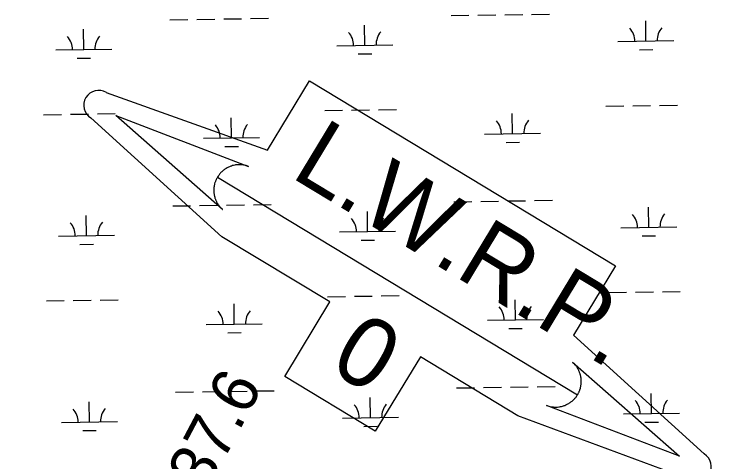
# Model space of a CAD drawing. Extents: x 3807117 to 3845308, y 337856 to 363736.
# Drawn here: x 3812085 to 3813343, y 356278 to 357078 of the extents above; entities that cross this region are included whole.
import ezdxf

# ---------------------------------------------------------------- set-up
doc = ezdxf.new("R2010")
doc.units = 0
for name, color, linetype in [('V-RIVR-EDGE', 7, 'Continuous'), ('V-RIVR-RANG-IDEN', 7, 'Continuous'), ('V-TOPO-WATR-IDEN', 7, 'Continuous'), ('V-WETL-SWMP', 7, 'Continuous')]:
    doc.layers.add(name, color=color, linetype=linetype)

msp = doc.modelspace()

# ---------------------------------------------------------------- linework, layer by layer
at = {"layer": 'V-RIVR-EDGE'}
msp.add_spline([(3811174.6, 356373.1), (3811188.7, 356370), (3811203.6, 356367.3), (3811222.1, 356356.8), (3811286.2, 356317.3), (3811338.6, 356278.8), (3811362.1, 356266.1), (3811376.1, 356260.1), (3811397.3, 356252.4), (3811428.9, 356236.1), (3811458.2, 356216.5), (3811472.2, 356207.9), (3811493.5, 356193.8), (3811502, 356194.7), (3811509.7, 356201), (3811518.8, 356201.5), (3811535.5, 356195.1), (3811546.8, 356183.3), (3811549.5, 356172.5), (3811555.8, 356158.4), (3811561.2, 356151.2), (3811563.9, 356150.7), (3811570.7, 356164.3), (3811577, 356167), (3811587, 356165.6), (3811593.3, 356157.4), (3811593.3, 356147.9), (3811590.5, 356127.6), (3811588.2, 356117.6), (3811588.2, 356110.9), (3811591.8, 356109.5), (3811595.9, 356113.1), (3811603.1, 356121.7), (3811609, 356123), (3811615.4, 356120.3), (3811626.2, 356116.2), (3811633, 356116.2), (3811652.9, 356117.9), (3811659.2, 356118.4), (3811668.7, 356112.9), (3811684.5, 356097.5), (3811704.8, 356068.5), (3811718.7, 356057.6), (3811733.2, 356054.4), (3811778.4, 356035.3), (3811810.9, 356009.5), (3811826.6, 355990.9), (3811837.5, 355972.8), (3811842.9, 355966.4), (3811851, 355959.6), (3811871.8, 355949.2), (3811884.4, 355946), (3811887.6, 355947.3), (3811894.8, 355959.1), (3811900.3, 355966.8), (3811904.4, 355968.1), (3811911.1, 355967.2), (3811933.7, 355960.3), (3811953.6, 355954.9), (3811968.1, 355948), (3811975.3, 355942.2), (3811975.3, 355934), (3811973.9, 355925.4), (3811965.3, 355923.6), (3811954.9, 355917.3), (3811954.4, 355912.8), (3811954.9, 355908.7), (3811959.4, 355907.8), (3811968.9, 355908.3), (3811984.7, 355910.5), (3811997.4, 355911.8), (3812006.4, 355911.3), (3812019.5, 355907.2), (3812036.2, 355901.8), (3812052.5, 355884.5), (3812061, 355876.8), (3812080.4, 355863.7), (3812103.4, 355838.7), (3812123.3, 355824.7), (3812150.9, 355811.5), (3812172.1, 355802.9), (3812200.5, 355791), (3812223.6, 355788.3), (3812292.7, 355755.5), (3812354.5, 355719.7), (3812388.9, 355704.2), (3812435.8, 355683.3), (3812470.2, 355669.6), (3812515.8, 355647.8), (3812561.9, 355627.4), (3812619.7, 355603.3), (3812627.3, 355597.4), (3812632.3, 355581.1), (3812642.2, 355563), (3812652.1, 355554.3), (3812664.7, 355545.3), (3812680.1, 355537.5), (3812689.6, 355537.5), (3812696.4, 355540.2), (3812708.6, 355557.4), (3812712.3, 355559.2), (3812718.6, 355558.7), (3812726.3, 355555.1), (3812727.2, 355547.8), (3812725.3, 355538.3), (3812726.2, 355531.1), (3812730.7, 355527.9), (3812741.6, 355524.7), (3812757.4, 355524.7), (3812770.1, 355528.7), (3812783.2, 355531), (3812801.3, 355531.4), (3812813.9, 355528.6), (3812818, 355524.1), (3812815.2, 355510.5), (3812814.8, 355503.3), (3812822, 355495.1), (3812833.7, 355491), (3812849.5, 355489.2), (3812854.5, 355488.7), (3812866.3, 355482.4), (3812885.7, 355473.3), (3812897.9, 355471), (3812923.2, 355457.8), (3812956.1, 355437.8), (3812980.5, 355421.9), (3813004, 355411.5), (3813028.8, 355399.2), (3813057.7, 355387.4), (3813082.6, 355380.1), (3813107, 355369.2), (3813115.1, 355361.9), (3813141.7, 355342.9), (3813152.5, 355328.4), (3813174.2, 355306.2), (3813192.7, 355289.8), (3813202.6, 355284.8), (3813208.5, 355285.3), (3813218, 355288), (3813230.7, 355292.9), (3813236.6, 355293.4), (3813245.1, 355289.7), (3813263.2, 355285.6), (3813267.7, 355285.1), (3813270, 355286.9), (3813270.5, 355301), (3813271.8, 355301.9), (3813276.8, 355300), (3813295.3, 355295.5), (3813313.4, 355290), (3813325.6, 355285.9), (3813339.2, 355274.6), (3813349.1, 355266.4), (3813373.5, 355254.1), (3813384.3, 355240.1), (3813390.1, 355227.4), (3813401.4, 355221.1), (3813410, 355220.1), (3813420.9, 355220.1), (3813425.4, 355215.6), (3813431.7, 355214.6), (3813438, 355215.1), (3813453, 355219.6), (3813462.9, 355219.5), (3813469.7, 355219.5), (3813510.8, 355200.9), (3813544.2, 355185.9), (3813556.4, 355177.7), (3813570.4, 355157.8), (3813577.6, 355151), (3813584.8, 355149.2), (3813595.7, 355149.6), (3813613.3, 355148.6), (3813625.5, 355148.6), (3813631.4, 355146.8), (3813632.7, 355144.1), (3813630, 355137.3), (3813633.2, 355133.7), (3813638.6, 355130.9), (3813640.8, 355124.1), (3813644.4, 355110.1), (3813651.6, 355103.3), (3813660.2, 355098.8), (3813674.7, 355096.9), (3813690.5, 355097.3), (3813700.9, 355096), (3813718.5, 355087.8), (3813718.5, 355082.4), (3813718.5, 355076), (3813722.5, 355072.9), (3813726.6, 355072.4), (3813733.4, 355078.7), (3813743.4, 355079.6), (3813752.4, 355079.6), (3813764.1, 355077.3), (3813775.4, 355072.3), (3813796.2, 355060.9), (3813812.9, 355052.3), (3813831, 355047.3), (3813835.5, 355047.3), (3813838.7, 355050.9), (3813845.5, 355051.8), (3813851.8, 355051.7), (3813864.5, 355049), (3813875.3, 355044), (3813890.7, 355036.3), (3813893.8, 355028.6), (3813896.5, 355015), (3813904.6, 355000.1), (3813910.4, 354995.5), (3813917.7, 354994.6), (3813923.6, 354996.4), (3813934.4, 355000.9), (3813943.9, 355000.9), (3813953.9, 354998.6), (3813958.8, 354990.9), (3813962.8, 354974.1), (3813969.6, 354969.6), (3813977.7, 354966), (3813995.8, 354961.9), (3814011.6, 354955.5), (3814029.3, 354950), (3814041.9, 354949.5), (3814070.9, 354953.5), (3814078.5, 354955.3), (3814093.5, 354953), (3814098.4, 354946.7), (3814098.8, 354934.5), (3814107.4, 354925), (3814114.6, 354922.7), (3814119.6, 354917.2), (3814117.8, 354903.2), (3814122.7, 354900.9), (3814126.8, 354900.9), (3814133.1, 354905.9), (3814137.7, 354908.1), (3814144.4, 354908.1), (3814158, 354902.7), (3814167.9, 354897.7), (3814183.7, 354889), (3814191.9, 354890.8), (3814207.3, 354894.9), (3814221.7, 354895.7), (3814233.5, 354890.7), (3814249.7, 354878), (3814256, 354862.2), (3814260.5, 354852.7), (3814273.6, 354845.9), (3814287.2, 354843.6), (3814299.8, 354843.5), (3814310.2, 354847.6), (3814334.2, 354848), (3814350.9, 354846.6), (3814373.5, 354840.6), (3814395.2, 354836.1), (3814414.6, 354829.7), (3814430, 354822.4), (3814448, 354805.6), (3814462.5, 354786.2), (3814479.6, 354775.7), (3814501.8, 354768.4), (3814528.4, 354754.3), (3814552.3, 354741.2), (3814565.4, 354730.3), (3814585.3, 354707.2), (3814597.9, 354689.5), (3814607.3, 354680.9), (3814616.4, 354674.6), (3814619.1, 354666.9), (3814617.2, 354657.4), (3814585.5, 354628.1), (3814583.2, 354619.9), (3814583.2, 354612.2), (3814590, 354602.3), (3814597.2, 354600.9), (3814603.5, 354601.3), (3814618, 354609.4), (3814627.5, 354613.9), (3814642, 354622.5), (3814658.3, 354631), (3814666.5, 354643.2), (3814680.1, 354662.2), (3814689.2, 354670.8), (3814695.5, 354672.5), (3814706.4, 354672.5), (3814718.6, 354671.6), (3814729.4, 354671.6), (3814744.3, 354669.3), (3814755.2, 354664.7), (3814764.2, 354652), (3814771.4, 354646.1), (3814784, 354641.6), (3814807.1, 354628), (3814826, 354619.8), (3814850.4, 354609.8), (3814882, 354591.6), (3814905.5, 354574.4), (3814916.8, 354561.2), (3814924.5, 354556.7), (3814939.4, 354556.2), (3814948.9, 354563), (3814953, 354567.5), (3814957, 354567.5), (3814966.1, 354557.9), (3814980.1, 354549.8), (3814987.7, 354549.7), (3814995.4, 354550.2), (3815006.7, 354552.9), (3815016.2, 354552.8), (3815022.1, 354551.5), (3815030.7, 354542.4), (3815042.9, 354538.8), (3815050.6, 354537.8), (3815065.5, 354531), (3815078.6, 354525.1), (3815103, 354515.1), (3815138.6, 354503.2), (3815160.8, 354496.4), (3815178.4, 354486.9), (3815184.7, 354486.9), (3815199.7, 354490), (3815209.2, 354489.5), (3815214.6, 354486.3), (3815223.1, 354477.7), (3815225.4, 354472.7), (3815220.8, 354463.7), (3815221.3, 354456.9), (3815225.3, 354451), (3815233.5, 354451), (3815240.7, 354457.3), (3815243, 354465), (3815248.4, 354469.1), (3815256.1, 354470.9), (3815267.9, 354470.4), (3815274.7, 354467.6), (3815278.7, 354467.6), (3815285.5, 354469), (3815295, 354469.9), (3815300.4, 354464.9), (3815300.9, 354455.4), (3815302.6, 354445.9), (3815313, 354440), (3815324.3, 354437.2), (3815330.2, 354436.8), (3815338.8, 354430.9), (3815351, 354418.6), (3815355.9, 354412.3), (3815365.9, 354409.1), (3815372.2, 354409.1), (3815382.1, 354402.3), (3815391.6, 354398.2), (3815392.5, 354396.4), (3815404.7, 354395.9), (3815419.2, 354395.8), (3815436.8, 354389.5), (3815445.4, 354379.5), (3815457.5, 354368.2), (3815473.8, 354360.4), (3815487.8, 354360.4), (3815509.1, 354365.8), (3815515.4, 354368), (3815523.1, 354373.4), (3815534.4, 354377.5), (3815545.7, 354377.4), (3815556.1, 354371.1), (3815567.4, 354358.4), (3815574.6, 354351.1), (3815578.7, 354351.1), (3815582.3, 354352), (3815589.5, 354353.4), (3815597.7, 354355.2), (3815605.4, 354352.9), (3815608, 354342), (3815617.5, 354323.9), (3815625.2, 354318.5), (3815645.9, 354311.6), (3815662.7, 354310.2), (3815681.7, 354308.4), (3815700.6, 354302.9)], degree=3, dxfattribs=at)
at = {"layer": 'V-TOPO-WATR-IDEN'}
msp.add_line((3812448.1, 356786.8), (3813090.9, 356398.1), dxfattribs=at)
for points in [[(3812249.6, 356937.8), (3812537.2, 356834.8), (3812612.1, 356958.7), (3813158.5, 356628.2), (3813083.6, 356504.4), (3813316.8, 356292.4)], [(3813289.4, 356247), (3812984.2, 356360.6), (3812810.2, 356465.9), (3812729.8, 356333), (3812568, 356430.8), (3812648.4, 356563.7), (3812456, 356680.1), (3812222.2, 356892.4)]]:
    msp.add_lwpolyline(points, dxfattribs=at)
for points in [[(3812456.9, 356728.9), (3812266.3, 356896.7), (3812503.5, 356805.9), (3812499.1, 356807.3), (3812494.8, 356808.2), (3812493.1, 356808.5), (3812491.5, 356808.7), (3812489.6, 356808.8), (3812487.8, 356808.9), (3812486.2, 356808.9), (3812484, 356808.8), (3812481.7, 356808.5), (3812480.4, 356808.4), (3812478.8, 356808.1), (3812476.6, 356807.6), (3812474.9, 356807.2), (3812473.2, 356806.6), (3812472, 356806.3), (3812470.8, 356805.8), (3812469.2, 356805.2), (3812467.9, 356804.6), (3812466.5, 356803.9), (3812465.4, 356803.3), (3812463.8, 356802.4), (3812462.3, 356801.5), (3812461.2, 356800.7), (3812459.8, 356799.7), (3812458.7, 356798.9), (3812457.7, 356798.1), (3812457, 356797.4), (3812455.9, 356796.4), (3812454.7, 356795.3), (3812453.7, 356794.3), (3812452.7, 356793.2), (3812451.8, 356792.1), (3812450.9, 356790.9), (3812450.2, 356789.9), (3812449.2, 356788.5), (3812448.1, 356786.8), (3812447.8, 356786.2), (3812447.3, 356785.4), (3812446.8, 356784.5), (3812446.3, 356783.5), (3812445.8, 356782.6), (3812445.4, 356781.7), (3812445, 356780.6), (3812444.6, 356779.8), (3812444.2, 356778.7), (3812443.8, 356777.6), (3812443.6, 356776.9), (3812443, 356774.9), (3812442.8, 356773.9), (3812442.6, 356773.2), (3812442.3, 356772), (3812442.2, 356770.9), (3812442, 356769.8), (3812441.8, 356768.4), (3812441.7, 356767.2), (3812441.6, 356766.2), (3812441.5, 356765.3), (3812441.5, 356764.2), (3812441.5, 356763.2), (3812441.5, 356762), (3812441.5, 356760.8), (3812441.6, 356759.5), (3812441.8, 356758), (3812441.9, 356756.9), (3812442.1, 356755.7), (3812442.3, 356754.5), (3812442.5, 356753.6), (3812442.7, 356752.5), (3812443.1, 356751), (3812443.1, 356750.9), (3812443.4, 356750), (3812443.6, 356749.4), (3812443.9, 356748.4), (3812444.3, 356747.2), (3812444.7, 356746.2), (3812445.1, 356745.4), (3812445.5, 356744.3), (3812446, 356743.3), (3812446.4, 356742.5), (3812446.9, 356741.6), (3812447.6, 356740.3), (3812448, 356739.6), (3812448.4, 356739), (3812448.7, 356738.5), (3812449.1, 356737.8), (3812449.7, 356737), (3812450.2, 356736.2), (3812450.8, 356735.4), (3812451.4, 356734.7), (3812452.2, 356733.7), (3812452.7, 356733.2), (3812453.5, 356732.3), (3812454.4, 356731.3), (3812455.1, 356730.5), (3812455.7, 356730), (3812456.2, 356729.5), (3812456.6, 356729.1)], [(3813082.1, 356456), (3813272.6, 356288.1), (3813035.5, 356378.9), (3813039.8, 356377.5), (3813044.2, 356376.6), (3813045.9, 356376.3), (3813047.5, 356376.2), (3813049.4, 356376), (3813051.2, 356376), (3813052.8, 356376), (3813054.9, 356376.1), (3813057.3, 356376.3), (3813058.5, 356376.5), (3813060.2, 356376.8), (3813062.4, 356377.2), (3813064, 356377.7), (3813065.8, 356378.2), (3813067, 356378.6), (3813068.2, 356379), (3813069.7, 356379.7), (3813071.1, 356380.3), (3813072.5, 356380.9), (3813073.6, 356381.5), (3813075.2, 356382.4), (3813076.6, 356383.3), (3813077.8, 356384.1), (3813079.1, 356385.1), (3813080.3, 356386), (3813081.3, 356386.8), (3813082, 356387.4), (3813083.1, 356388.4), (3813084.2, 356389.5), (3813085.2, 356390.6), (3813086.2, 356391.7), (3813087.1, 356392.7), (3813088.1, 356393.9), (3813088.8, 356394.9), (3813089.8, 356396.4), (3813090.9, 356398.1), (3813091.2, 356398.6), (3813091.7, 356399.4), (3813092.2, 356400.4), (3813092.7, 356401.3), (3813093.1, 356402.2), (3813093.5, 356403.2), (3813094, 356404.3), (3813094.3, 356405), (3813094.8, 356406.2), (3813095.1, 356407.2), (3813095.4, 356408), (3813095.9, 356409.9), (3813096.2, 356411), (3813096.4, 356411.7), (3813096.6, 356412.9), (3813096.8, 356414), (3813097, 356415.1), (3813097.2, 356416.4), (3813097.3, 356417.7), (3813097.4, 356418.7), (3813097.4, 356419.5), (3813097.5, 356420.6), (3813097.5, 356421.7), (3813097.5, 356422.9), (3813097.4, 356424.1), (3813097.3, 356425.3), (3813097.2, 356426.8), (3813097.1, 356427.9), (3813096.9, 356429.1), (3813096.7, 356430.3), (3813096.5, 356431.3), (3813096.2, 356432.3), (3813095.9, 356433.8), (3813095.8, 356433.9), (3813095.6, 356434.8), (3813095.4, 356435.5), (3813095.1, 356436.4), (3813094.6, 356437.6), (3813094.3, 356438.6), (3813093.9, 356439.5), (3813093.4, 356440.5), (3813093, 356441.6), (3813092.6, 356442.3), (3813092.1, 356443.2), (3813091.4, 356444.5), (3813091, 356445.3), (3813090.6, 356445.8), (3813090.3, 356446.4), (3813089.9, 356447), (3813089.3, 356447.8), (3813088.8, 356448.6), (3813088.2, 356449.4), (3813087.6, 356450.2), (3813086.8, 356451.1), (3813086.3, 356451.7), (3813085.5, 356452.6), (3813084.6, 356453.6), (3813083.8, 356454.3), (3813083.3, 356454.9), (3813082.7, 356455.4), (3813082.4, 356455.7)]]:
    msp.add_lwpolyline(points, close=True, dxfattribs=at)
for centre, start, end in [((3812235.9, 356915.1), 58.8357, 238.8357), ((3813303.1, 356269.7), 238.8357, 58.8357)]:
    msp.add_arc(centre, 26.5, start, end, dxfattribs=at)
at = {"layer": 'V-WETL-SWMP'}
for p, q in [((3812865, 357075.3), (3812897, 357075.8)), ((3812913, 357076.1), (3812944.9, 357076.5)), ((3812960.9, 357076.8), (3812992.9, 357077.2)), ((3813008.9, 357077.5), (3813040.9, 357078)), ((3812363.1, 357067.8), (3812395.1, 357068.3)), ((3812411.1, 357068.5), (3812443.1, 357069)), ((3812459.1, 357069.3), (3812491.1, 357069.7)), ((3812507.1, 357070), (3812539.1, 357070.4)), ((3813213, 357029.8), (3813212.5, 357065.8)), ((3812209.3, 357014.8), (3812208.8, 357050.8)), ((3812711.1, 357022.3), (3812710.6, 357058.3)), ((3813163, 357029), (3813263, 357030.5)), ((3812159.3, 357014), (3812259.3, 357015.5)), ((3812661.1, 357021.5), (3812761.1, 357023)), ((3813201.2, 357014.2), (3813225.2, 357014.5)), ((3812197.5, 356999.2), (3812221.5, 356999.5)), ((3812699.4, 357006.7), (3812723.4, 357007)), ((3813141.3, 356913.3), (3813173.3, 356913.8)), ((3813189.3, 356914), (3813221.3, 356914.5)), ((3813237.3, 356914.7), (3813269.3, 356915.2)), ((3812137.6, 356898.2), (3812169.6, 356898.7)), ((3812185.6, 356899), (3812217.6, 356899.4)), ((3812233.6, 356899.7), (3812265.6, 356900.2)), ((3812639.5, 356905.8), (3812671.5, 356906.2)), ((3812687.5, 356906.5), (3812719.5, 356907)), ((3812735.5, 356907.2), (3812767.5, 356907.7)), ((3812975, 356864.4), (3812974.4, 356900.3)), ((3812473.1, 356856.8), (3812472.6, 356892.8)), ((3812925, 356863.6), (3813025, 356865.1)), ((3812423.1, 356856.1), (3812523.1, 356857.6)), ((3812963.2, 356848.7), (3812987.2, 356849.1)), ((3812461.4, 356841.2), (3812485.4, 356841.6)), ((3812368.1, 356735.2), (3812400.1, 356735.7)), ((3812416.1, 356735.9), (3812448.1, 356736.4)), ((3812464.1, 356736.6), (3812496.1, 356737.1)), ((3812512.1, 356737.3), (3812544.1, 356737.8)), ((3812869.9, 356742.7), (3812901.9, 356743.2)), ((3812917.9, 356743.4), (3812949.9, 356743.9)), ((3812965.9, 356744.1), (3812997.9, 356744.6)), ((3813013.9, 356744.9), (3813045.9, 356745.3)), ((3812716.1, 356689.6), (3812715.6, 356725.6)), ((3813218, 356697.2), (3813217.4, 356733.2)), ((3812214.3, 356682.1), (3812213.7, 356718.1)), ((3813168, 356696.4), (3813268, 356697.9)), ((3812666.1, 356688.9), (3812766.1, 356690.4)), ((3812164.3, 356681.4), (3812264.3, 356682.9)), ((3812704.4, 356674), (3812728.4, 356674.4)), ((3813206.2, 356681.6), (3813230.2, 356681.9)), ((3812202.5, 356666.5), (3812226.5, 356666.9)), ((3812644.5, 356573.1), (3812676.5, 356573.6)), ((3812692.5, 356573.8), (3812724.4, 356574.3)), ((3812740.4, 356574.6), (3812772.4, 356575)), ((3813146.3, 356580.6), (3813178.3, 356581.1)), ((3813194.3, 356581.4), (3813226.3, 356581.8)), ((3813242.3, 356582.1), (3813274.3, 356582.6)), ((3812142.6, 356565.6), (3812174.6, 356566.1)), ((3812190.6, 356566.3), (3812222.6, 356566.8)), ((3812238.6, 356567), (3812270.6, 356567.5)), ((3812478.1, 356524.2), (3812477.6, 356560.2)), ((3812980, 356531.7), (3812979.4, 356567.7)), ((3812428.1, 356523.4), (3812528.1, 356524.9)), ((3812930, 356531), (3813030, 356532.5)), ((3812466.3, 356508.6), (3812490.3, 356508.9)), ((3812968.2, 356516.1), (3812992.2, 356516.5)), ((3812874.9, 356410.1), (3812906.9, 356410.5)), ((3812922.9, 356410.8), (3812954.9, 356411.3)), ((3812970.9, 356411.5), (3813002.9, 356412)), ((3813018.9, 356412.2), (3813050.9, 356412.7)), ((3812373.1, 356402.5), (3812405.1, 356403)), ((3812421.1, 356403.3), (3812453.1, 356403.7)), ((3812469.1, 356404), (3812501.1, 356404.5)), ((3812517.1, 356404.7), (3812549.1, 356405.2)), ((3813223, 356364.5), (3813222.4, 356400.5)), ((3812219.3, 356349.5), (3812218.7, 356385.5)), ((3812721.1, 356357), (3812720.6, 356393)), ((3812671.1, 356356.3), (3812771.1, 356357.8)), ((3813173, 356363.8), (3813273, 356365.3)), ((3812169.3, 356348.7), (3812269.3, 356350.2)), ((3813211.2, 356348.9), (3813235.2, 356349.3)), ((3812207.5, 356333.9), (3812231.5, 356334.2)), ((3812709.3, 356341.4), (3812733.3, 356341.8))]:
    msp.add_line(p, q, dxfattribs=at)
for centre, start, end in [((3813157.8, 357029.4), 0.0865, 41.6302), ((3813268.2, 357031.1), 140.0865, 181.6302), ((3812154, 357014.4), 0.0865, 41.6302), ((3812264.5, 357016.1), 140.0865, 181.6302), ((3812655.9, 357021.9), 0.0865, 41.6302), ((3812766.4, 357023.6), 140.0865, 181.6302), ((3812919.7, 356864), 0.0865, 41.6302), ((3813030.2, 356865.7), 140.0865, 181.6302), ((3812417.9, 356856.5), 0.0865, 41.6302), ((3812528.4, 356858.1), 140.0865, 181.6302), ((3812660.9, 356689.3), 0.0865, 41.6302), ((3812771.4, 356690.9), 140.0865, 181.6302), ((3813162.7, 356696.8), 0.0865, 41.6302), ((3813273.2, 356698.5), 140.0865, 181.6302), ((3812159, 356681.8), 0.0865, 41.6302), ((3812269.5, 356683.4), 140.0865, 181.6302), ((3812422.9, 356523.8), 0.0865, 41.6302), ((3812533.3, 356525.5), 140.0865, 181.6302), ((3812924.7, 356531.4), 0.0865, 41.6302), ((3813035.2, 356533), 140.0865, 181.6302), ((3813167.7, 356364.2), 0.0865, 41.6302), ((3813278.2, 356365.8), 140.0865, 181.6302), ((3812164, 356349.1), 0.0865, 41.6302), ((3812274.5, 356350.8), 140.0865, 181.6302), ((3812665.9, 356356.7), 0.0865, 41.6302), ((3812776.3, 356358.3), 140.0865, 181.6302)]:
    msp.add_arc(centre, 35.2, start, end, dxfattribs=at)

# ---------------------------------------------------------------- texts
at = {"layer": 'V-RIVR-RANG-IDEN'}
msp.add_text('R-37.6', height=83, rotation=62.1413, dxfattribs=at).set_placement((3812373.7, 356118.3))
at = {"layer": 'V-TOPO-WATR-IDEN'}
for s, rotation, p in [('L.W.R.P.', 328.8356, (3812576.4, 356788.1)), ('0', 328.8357, (3812643.6, 356444.2))]:
    msp.add_text(s, height=124.5, rotation=rotation, dxfattribs=at).set_placement(p)

doc.saveas('drawing.dxf')
